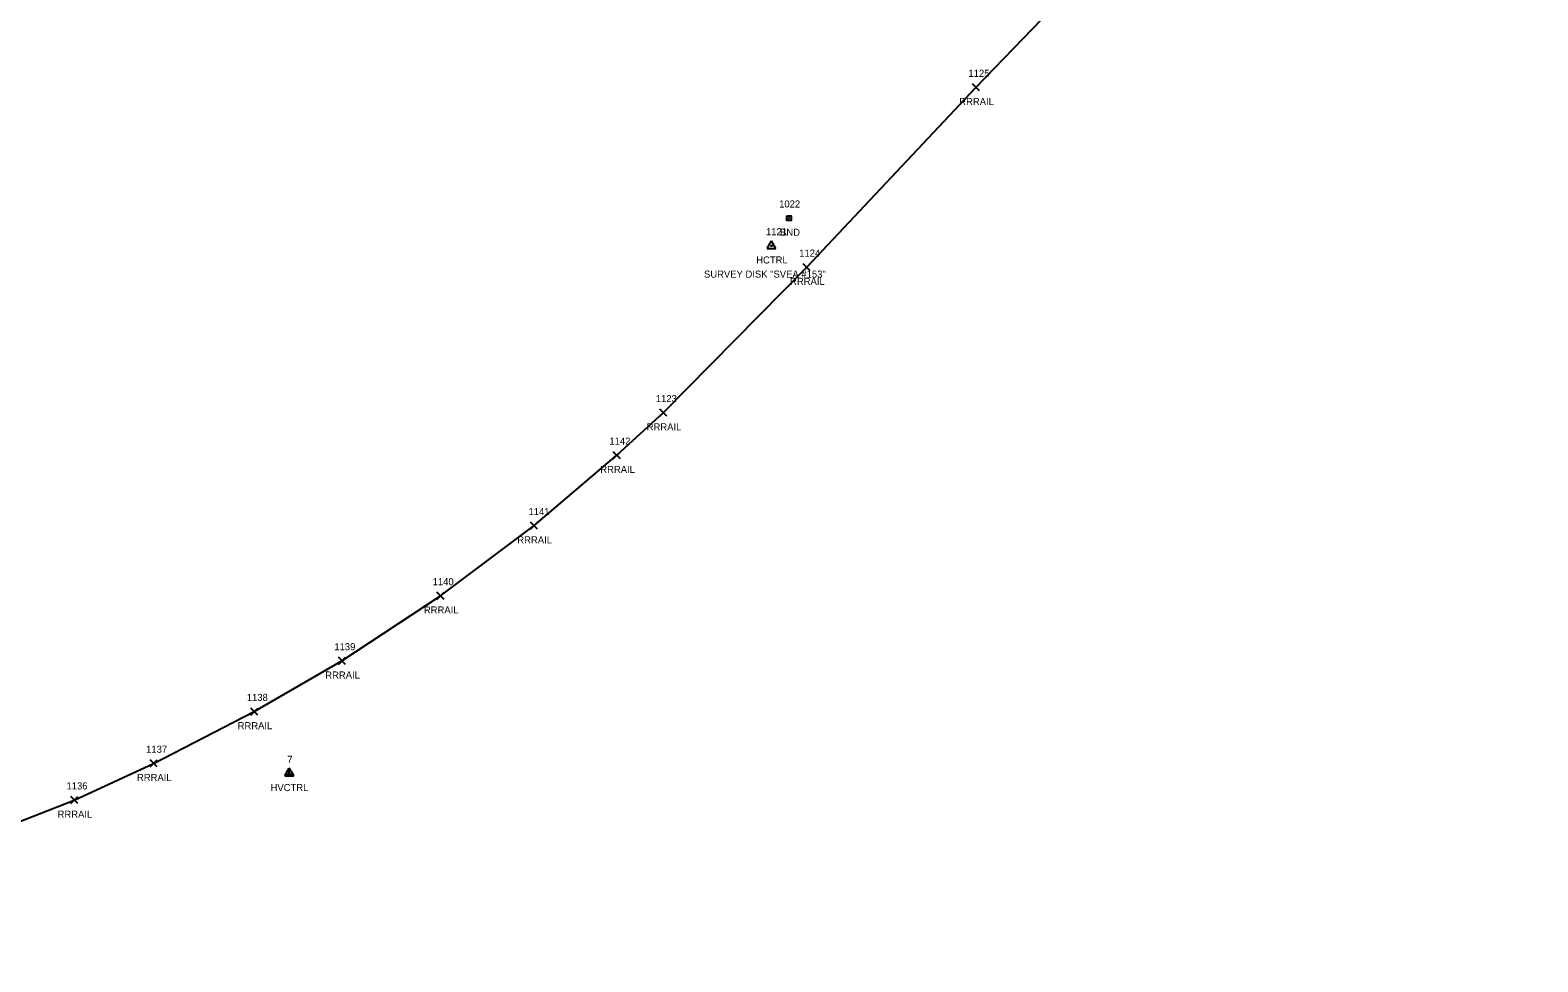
# Model space of a CAD drawing. Extents: x 1764889 to 1767296, y 695936 to 698960.
# Drawn here: x 1765682.8 to 1766109.4, y 695957.2 to 696220.7 of the extents above; entities that cross this region are included whole.
import ezdxf

# ---------------------------------------------------------------- set-up
doc = ezdxf.new("R2010")
doc.units = 0
for name, color, linetype in [('C_A', 7, 'Continuous'), ('C_C', 7, 'Continuous'), ('C_I', 7, 'Continuous'), ('CPH', 7, 'Continuous'), ('CPSM', 7, 'Continuous'), ('Level 18', 7, 'Continuous'), ('M_A', 7, 'Continuous'), ('M_I', 7, 'Continuous'), ('R_A', 7, 'Continuous'), ('R_I', 7, 'Continuous'), ('R_TIC', 7, 'Continuous'), ('RR', 7, 'Continuous')]:
    doc.layers.add(name, color=color, linetype=linetype)

msp = doc.modelspace()

# ---------------------------------------------------------------- linework, layer by layer
at = {"layer": 'CPH'}
for p, q in [((1765891.29, 696158.99), (1765892.54, 696161.16)), ((1765891.29, 696158.99), (1765893.79, 696158.99)), ((1765893.79, 696158.99), (1765892.54, 696161.16)), ((1765892.54, 696159.71), (1765892.54, 696159.71))]:
    msp.add_line(p, q, dxfattribs=at)
msp.add_circle((1765892.54, 696159.71), 0.0833, dxfattribs=at)
at = {"layer": 'CPSM'}
for p, q in [((1765754.85, 696009.74), (1765756.1, 696011.9)), ((1765754.85, 696009.74), (1765756.1, 696011.9)), ((1765754.85, 696009.74), (1765756.1, 696011.9)), ((1765754.85, 696009.74), (1765756.1, 696010.46)), ((1765754.85, 696009.74), (1765756.1, 696010.46)), ((1765754.85, 696009.74), (1765756.1, 696010.46)), ((1765754.85, 696009.74), (1765757.35, 696009.74)), ((1765754.85, 696009.74), (1765757.35, 696009.74)), ((1765754.85, 696009.74), (1765757.35, 696009.74)), ((1765757.35, 696009.74), (1765756.1, 696011.9)), ((1765756.1, 696010.46), (1765756.1, 696011.9)), ((1765757.35, 696009.74), (1765756.1, 696011.9)), ((1765756.1, 696010.46), (1765756.1, 696011.9)), ((1765757.35, 696009.74), (1765756.1, 696011.9)), ((1765756.1, 696010.46), (1765756.1, 696011.9)), ((1765756.1, 696010.46), (1765756.1, 696010.46)), ((1765756.1, 696010.46), (1765757.35, 696009.74)), ((1765756.1, 696010.46), (1765756.1, 696010.46)), ((1765756.1, 696010.46), (1765757.35, 696009.74)), ((1765756.1, 696010.46), (1765756.1, 696010.46)), ((1765756.1, 696010.46), (1765757.35, 696009.74))]:
    msp.add_line(p, q, dxfattribs=at)
at = {"layer": 'Level 18'}
msp.add_lwpolyline([(1765896.84, 696168.18), (1765898.09, 696168.18), (1765898.09, 696166.92), (1765896.84, 696166.92)], close=True, dxfattribs=at)
msp.add_circle((1765897.47, 696167.55), 0.0833, dxfattribs=at)
at = {"layer": 'R_TIC'}
for points in [[(1765949.39, 696203.51), (1765951.39, 696205.51)], [(1765951.39, 696203.51), (1765949.39, 696205.51)], [(1765901.5, 696152.66), (1765903.5, 696154.66)], [(1765903.5, 696152.66), (1765901.5, 696154.66)], [(1765860.93, 696111.49), (1765862.93, 696113.49)], [(1765862.93, 696111.49), (1765860.93, 696113.49)], [(1765860.93, 696111.49), (1765862.93, 696113.49)], [(1765862.93, 696111.49), (1765860.93, 696113.49)], [(1765847.78, 696099.46), (1765849.78, 696101.46)], [(1765849.78, 696099.46), (1765847.78, 696101.46)], [(1765847.78, 696099.46), (1765849.78, 696101.46)], [(1765849.78, 696099.46), (1765847.78, 696101.46)], [(1765824.33, 696079.52), (1765826.33, 696081.52)], [(1765826.33, 696079.52), (1765824.33, 696081.52)], [(1765797.88, 696059.7), (1765799.88, 696061.7)], [(1765799.88, 696059.7), (1765797.88, 696061.7)], [(1765769.97, 696041.3), (1765771.97, 696043.3)], [(1765771.97, 696041.3), (1765769.97, 696043.3)], [(1765745.18, 696026.96), (1765747.18, 696028.96)], [(1765747.18, 696026.96), (1765745.18, 696028.96)], [(1765716.69, 696012.3), (1765718.69, 696014.3)], [(1765718.69, 696012.3), (1765716.69, 696014.3)], [(1765694.23, 696001.92), (1765696.23, 696003.92)], [(1765696.23, 696001.92), (1765694.23, 696003.92)]]:
    msp.add_lwpolyline(points, dxfattribs=at)
at = {"layer": 'RR'}
for points in [[(1765861.93, 696112.49), (1765902.5, 696153.66), (1765950.39, 696204.51), (1765987.77, 696243.31), (1766027.17, 696281.97), (1766064.51, 696314.67), (1766109.4, 696350.61)], [(1765861.93, 696112.49), (1765848.78, 696100.46)], [(1765485.89, 695957.16), (1765530.77, 695959.99), (1765574.28, 695966.35), (1765622.7, 695977.44), (1765659.71, 695989.05), (1765695.23, 696002.92), (1765717.69, 696013.3), (1765746.18, 696027.96), (1765770.97, 696042.3), (1765798.88, 696060.7), (1765825.33, 696080.52), (1765848.78, 696100.46)]]:
    msp.add_lwpolyline(points, dxfattribs=at)

# ---------------------------------------------------------------- texts
at = {"layer": 'C_A'}
for s, p in [('HCTRL', (1765888.21, 696154.71)), ('HVCTRL', (1765750.79, 696005.46)), ('HVCTRL', (1765750.79, 696005.46)), ('HVCTRL', (1765750.79, 696005.46))]:
    msp.add_text(s, height=2, dxfattribs=at).set_placement(p)
at = {"layer": 'C_C'}
msp.add_text('SURVEY DISK "SVEA #153"', height=2, dxfattribs=at).set_placement((1765873.44, 696150.71))
at = {"layer": 'C_I'}
for s, p in [('1121', (1765890.98, 696162.71)), ('7', (1765755.53, 696013.46)), ('7', (1765755.53, 696013.46)), ('7', (1765755.53, 696013.46))]:
    msp.add_text(s, height=2, dxfattribs=at).set_placement(p)
at = {"layer": 'M_A'}
msp.add_text('BND', height=2, dxfattribs=at).set_placement((1765894.96, 696162.55))
at = {"layer": 'M_I'}
msp.add_text('1022', height=2, dxfattribs=at).set_placement((1765894.7, 696170.55))
at = {"layer": 'R_A'}
for p in [(1765945.68, 696199.51), (1765897.79, 696148.66), (1765857.23, 696107.49), (1765857.23, 696107.49), (1765844.08, 696095.46), (1765844.08, 696095.46), (1765820.62, 696075.52), (1765794.17, 696055.7), (1765766.27, 696037.3), (1765741.47, 696022.96), (1765712.98, 696008.3), (1765690.52, 695997.92)]:
    msp.add_text('RRRAIL', height=2, dxfattribs=at).set_placement(p)
at = {"layer": 'R_I'}
for s, p in [('1125', (1765948.27, 696207.51)), ('1124', (1765900.38, 696156.66)), ('1123', (1765859.81, 696115.49)), ('1123', (1765859.81, 696115.49)), ('1142', (1765846.66, 696103.46)), ('1142', (1765846.66, 696103.46)), ('1141', (1765823.77, 696083.52)), ('1140', (1765796.66, 696063.7)), ('1139', (1765768.84, 696045.3)), ('1138', (1765744.06, 696030.96)), ('1137', (1765715.57, 696016.3)), ('1136', (1765693.05, 696005.92))]:
    msp.add_text(s, height=2, dxfattribs=at).set_placement(p)

doc.saveas('drawing.dxf')
